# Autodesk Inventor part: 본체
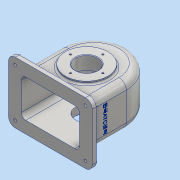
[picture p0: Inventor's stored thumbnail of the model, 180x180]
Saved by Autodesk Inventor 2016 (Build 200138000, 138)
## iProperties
Created: 2018-11
Part Number: 본체
Material: 알루미늄 6061
Document SubType Name: Modeling
Designer: 공506_39
Density: 2.7 g/cm^3
Appearance: 알루미늄 - 평지
Mass: 1091.93 g
Surface Area: 1182.25 cm^2
Volume: 404.42 cm^3
Author: 공506_39
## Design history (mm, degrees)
sketch "스케치2"
  geometry: L1 (-58, 0)-(58, 0); L2 (58, 0)-(58, -78); L3 (58, -78)-(-58, -78); L4 (-58, -78)-(-58, 0); A1 r 58 centre (0, 0) between (58, 0) and (-58, 0); 1 further point
  constraints: 8 end point, 2 parallel, 2 point on circle, 2 tangent, 1 centre point, 1 coincident, 1 horizontal, 1 perpendicular
  dimensions: "d0" = 116 diameter of A1; "d1" = 78 distance between parallel lines of L1 L3
extrude "돌출1" new body sketch "스케치2" distance "d2" = 77; taper "d3" = 0 deg
fillet "모깎기1" dims "d4" = 13
sketch "스케치3"
  geometry: L1 (103, -13)-(103, -64) reference; L2 (90, 0)-(0, 0) reference; L3 (-13, -13)-(-13, -64) reference; L4 (90, -77)-(0, -77) reference; L5 (-30, 16.5)-(120, 16.5); L6 (120, 16.5)-(120, -93.5); L7 (120, -93.5)-(-30, -93.5); L8 (-30, -93.5)-(-30, 16.5); L9 (-30, 16.5)-(120, -93.5); L10 (120, 16.5)-(-30, -93.5); A1 r 13 centre (90, -64) between (90, -77) and (103, -64) reference; A2 r 13 centre (90, -13) between (103, -13) and (90, 0) reference; A3 r 13 centre (0, -13) between (0, 0) and (-13, -13) reference; A4 r 13 centre (0, -64) between (-13, -64) and (0, -77) reference; 6 further points
  constraints: 12 end point, 6 midpoint, 2 parallel, 1 horizontal, 1 horizontal alignment, 1 perpendicular, 1 vertical alignment
  dimensions: "d6" = 110 distance of L5.end L6.end; "d7" = 150 distance of L6.end L7.end
extrude "돌출2" join sketch "스케치3" distance "d8" = 10; taper "d9" = 0 deg
fillet "모깎기2" dims "d10" = 12
node "작업 평면1"
sketch "스케치4"
  geometry: L1 (5, -80.5)-(121, -80.5) reference; L2 (5, -29.5)-(5, -80.5) reference; L3 (121, -29.5)-(5, -29.5) reference; L4 (121, -29.5)-(121, -80.5) reference; L5 (0, 0)-(126, 0) reference; L6 (138, -12)-(138, -98) reference; C1 r 6 at (63, -55); 1 further point
  constraints: 1 centre point
  dimensions: "d12" = 55 distance from line of L5 C1.centre; "d13" = 75 distance from line of L6 C1.centre; "d14" = 12 diameter of C1
extrude "돌출3" join sketch "스케치4" stored distance "d15" = 10; taper "d16" = 5 deg
sketch "스케치5"
  geometry: L1 (-63, -78)-(63, -78) reference; C1 r 38 at (0, -13); 1 further point
  constraints: 1 centre point, 1 vertical alignment
  dimensions: "d17" = 76 diameter of C1; "d18" = 65 distance from line of L1 C1.centre
extrude "돌출4" join sketch "스케치5" distance "d19" = 5; taper "d20" = 0 deg
node "작업 평면2"
node "작업 평면3"
sketch "스케치11"
  geometry: L1 (108, 93.5)-(-18, 93.5) reference; L2 (-30, 81.5)-(-30, -4.5) reference; L3 (-18, -16.5)-(108, -16.5) reference; L4 (120, -4.5)-(120, 81.5) reference; L5 (103, 13)-(103, 64) reference; L6 (0, 0)-(90, 0) reference; L7 (-13, 64)-(-13, 13) reference; L8 (90, 77)-(0, 77) reference; A1 r 12 centre (108, 81.5) between (120, 81.5) and (108, 93.5) reference; A2 r 12 centre (-18, 81.5) between (-18, 93.5) and (-30, 81.5) reference; A3 r 12 centre (-18, -4.5) between (-30, -4.5) and (-18, -16.5) reference; A4 r 12 centre (108, -4.5) between (108, -16.5) and (120, -4.5) reference; A5 r 13 centre (90, 13) between (90, 0) and (103, 13) reference; A6 r 13 centre (0, 13) between (-13, 13) and (0, 0) reference; A7 r 13 centre (0, 64) between (0, 77) and (-13, 64) reference; A8 r 13 centre (90, 64) between (103, 64) and (90, 77) reference; 5 further points
  constraints: 4 coincident
hole "구멍1" sketch "스케치11" at (-18, -4.5), (-18, 81.5), (108, 81.5), (108, -4.5) diameter "d35" = 5; stored, may be unused: countersink angle "d39" = 90 deg, drill point angle "d41" = 118 deg; dims "d36" = 6, "d37" = 12, "d38" = 4, "d40" = 8
node "작업 평면4"
hole "구멍4" diameter "d66" = 4.459; stored, may be unused: countersink angle "d70" = 90 deg, drill point angle "d72" = 118 deg; dims "d64" = 10, "d65" = 10, "d67" = 20, "d68" = 12, "d69" = 4, "d71" = 12.8
fillet "모깎기3" dims "d73" = 3
node "작업 평면5"
sketch "스케치16"
  geometry: L1 (58, 0)-(58, -65) reference; L2 (-58, -65)-(-58, 0) reference; L3 (0, 0)-(0, -121); L4 (-52, 0)-(-52, -121); L5 (52, -121)-(52, 0); A1 r 58 centre (0, 0) between (58, 0) and (-58, 0) reference; A2 r 52 centre (0, 0) between (52, 0) and (-52, 0); A3 r 52 centre (0, -121) between (-52, -121) and (52, -121); 2 further points
  constraints: 8 end point, 4 point on circle, 4 tangent, 2 centre point, 1 midpoint, 1 parallel, 1 vertical
  dimensions: "d74" = 6 radial gap between concentric circles of A1 A2; "d75" = 121 distance of L3.start L3.end
extrude "돌출8" cut sketch "스케치16" stored distance "d76" = 67; taper "d77" = 0 deg
node "작업 평면6"
sketch "스케치17"
  geometry: C1 r 38 at (0, 0) reference; C2 r 28 at (0, 0); 1 further point
  constraints: 1 centre point, 1 coincident
  dimensions: "d79" = 56 diameter of C2
extrude "돌출9" join sketch "스케치17" stored distance "d80" = 67; taper "d81" = 40 deg
sketch "스케치19"
  geometry: L1 (0, 0)-(0, 29); C1 r 38 at (0, 0) reference; 2 further points
  constraints: 2 end point, 1 coincident, 1 point on line, 1 vertical
  dimensions: "d82" = 29 distance of L1.start L1.end
hole "구멍5" sketch "스케치19" at (0, 29) diameter "d83" = 3.242; stored, may be unused: countersink angle "d87" = 90 deg, drill point angle "d89" = 118 deg; dims "d84" = 8, "d85" = 12, "d86" = 4, "d88" = 10
sketch "스케치20"
  geometry: C1 r 38 at (0, -13) reference; C2 r 38 at (0, -13); 1 further point
  constraints: 1 centre point, 1 coincident
  dimensions: "d94" = 76 diameter of C2
extrude "돌출10" join sketch "스케치20" stored distance "d95" = 67; taper "d96" = 0 deg
sketch "스케치21"
  geometry: L1 (0, 0)-(0, 29); C1 r 38 at (0, 0) reference; 2 further points
  constraints: 2 end point, 1 coincident, 1 vertical
  dimensions: "d97" = 29 distance of L1.start L1.end
hole "구멍6" sketch "스케치21" at (0, 29) diameter "d98" = 3.242; stored, may be unused: countersink angle "d102" = 90 deg, drill point angle "d104" = 118 deg; dims "d99" = 8, "d100" = 12, "d101" = 4, "d103" = 10
sketch "스케치22"
  geometry: C1 r 1.621 at (29, 0) reference; C2 r 1.621 at (0, -29) reference; C3 r 1.621 at (-29, 0) reference; C4 r 1.621 at (0, 29) reference; C5 r 38 at (0, 0) reference; 2 further points
  constraints: 1 coincident
hole "구멍7" sketch "스케치22" at (0, 0) diameter "d108" = 40; stored, may be unused: countersink angle "d112" = 90 deg, drill point angle "d114" = 118 deg; dims "d109" = 8, "d110" = 12, "d111" = 4, "d113" = 10
chamfer "모따기2" distance "d115" = 1; stored, may be unused: second distance "d116" = 2, angle "d117" = 45 deg
fillet "모깎기4" dims "d118" = 3
fillet "모깎기5" dims "d119" = 8
fillet "모깎기6" dims "d120" = 3
sketch "스케치23"
  geometry: L1 (-17.5, -78)-(68.5, -78) reference; L2 (80.5, -78)-(80.5, -71) reference; L3 (-29.5, -71)-(-29.5, -78) reference; L4 (-13, 0)-(-13, -65) reference; 2 further points
  constraints: 1 coincident, 1 other
  dimensions: "d123" = 40 distance from line of L1 point (25.5, -38); "d125" = 38.5 distance from line of point (25.5, -38) L4
feature "엠보싱1" sketch "스케치23" dims "d126" = 0.5, "d127" = 0
node "솔리드1"
pattern_circular "원형 패턴3" dims angle "d91" = 360 deg
pattern_circular "원형 패턴4" dims angle "d106" = 360 deg
node "투영된 루프1"
node "투영된 루프2"
node "투영된 루프6"
node "투영된 루프9"
node "투영된 루프10"
node "투영된 루프11"
other parameters: "d11" = -142, "d21" = -24, "d25" = -87, "d78" = -24
